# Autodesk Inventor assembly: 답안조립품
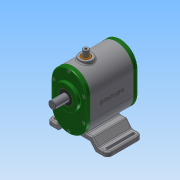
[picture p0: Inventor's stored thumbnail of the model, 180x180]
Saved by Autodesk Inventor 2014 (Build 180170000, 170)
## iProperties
Created: 2018-07
Part Number: 답안조립품
Document SubType Name: Assembly
Designer: SEO-12
Mass: 2422.76 g
Surface Area: 2005.93 cm^2
Volume: 678.327 cm^3
Density: 3.57167 g/cm^3
Author: SEO-12
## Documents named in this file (14)
- C:\Users\SEO-12\Desktop\380708V1015\답안조립품.iam
- C:\Users\SEO-12\Desktop\380708V1015\본체.ipt
- C:\Users\SEO-12\Desktop\380708V1015\가변스프링.ipt
- C:\Users\SEO-12\Desktop\380708V1015\뒤커버.ipt
- C:\Users\SEO-12\Desktop\380708V1015\메인축.ipt
- C:\Users\SEO-12\Desktop\380708V1015\베어링 608.ipt
- C:\Users\SEO-12\Desktop\380708V1015\베어링 6003.ipt
- C:\Users\SEO-12\Desktop\380708V1015\볼트 M4.ipt
- C:\Users\SEO-12\Desktop\380708V1015\부시.ipt
- C:\Users\SEO-12\Desktop\380708V1015\서브축.ipt
- C:\Users\SEO-12\Desktop\380708V1015\슬라이더.ipt
- C:\Users\SEO-12\Desktop\380708V1015\앞커버.ipt
- C:\Users\SEO-12\Desktop\380708V1015\오일 실 8 22 7.ipt
- C:\Users\SEO-12\Desktop\380708V1015\오일 실 17 32 8.ipt
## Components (1 placed, 1 different names)
1. 가변스프링:1
